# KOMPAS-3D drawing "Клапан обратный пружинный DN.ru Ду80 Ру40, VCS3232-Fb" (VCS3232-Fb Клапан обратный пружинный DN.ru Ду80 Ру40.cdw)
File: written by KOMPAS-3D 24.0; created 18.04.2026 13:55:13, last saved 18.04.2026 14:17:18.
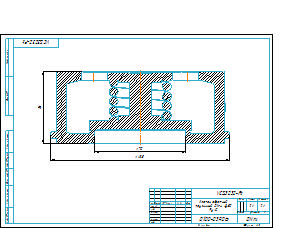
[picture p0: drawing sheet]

Document properties: c3d_UniqueCompID: 071bd168-1a06-425c-849c-e99e84a96128; Наименование: Деталь; Автор: 712; Класс точности: c; Знак неуказанной шероховатости: Шероховатость не задана; Рассекать на разрезах: Да; c3d_UniqueCompID: 071bd168-1a06-425c-849c-e99e84a96128; Наименование: Деталь; Автор: 712; Класс точности: c; Знак неуказанной шероховатости: Шероховатость не задана; Рассекать на разрезах: Да; c3d_UniqueCompID: 071bd168-1a06-425c-849c-e99e84a96128; Наименование: Деталь; Автор: 712; Класс точности: c; Знак неуказанной шероховатости: Шероховатость не задана; Рассекать на разрезах: Да; c3d_UniqueCompID: 071bd168-1a06-425c-849c-e99e84a96128; Наименование: Деталь; Автор: 712; Класс точности: c; Знак неуказанной шероховатости: Шероховатость не задана; Рассекать на разрезах: Да; c3d_UniqueCompID: 071bd168-1a06-425c-849c-e99e84a96128; Наименование: Деталь; Автор: 712; Класс точности: c; Знак неуказанной шероховатости: Шероховатость не задана; Рассекать на разрезах: Да; c3d_UniqueCompID: 071bd168-1a06-425c-849c-e99e84a96128; Наименование: Деталь; Автор: 712; Класс точности: c; Знак неуказанной шероховатости: Шероховатость не задана; Рассекать на разрезах: Да; c3d_UniqueCompID: 071bd168-1a06-425c-849c-e99e84a96128; Наименование: Деталь; Автор: 712; Класс точности: c; Знак неуказанной шероховатости: Шероховатость не задана; Рассекать на разрезах: Да; c3d_UniqueCompID: 071bd168-1a06-425c-849c-e99e84a96128; Наименование: Деталь; Автор: 712; Класс точности: c; Знак неуказанной шероховатости: Шероховатость не задана; Рассекать на разрезах: Да; Автор: 712; Форматы листов документа: A3; Полное имя файла: VCS3232-Fb Клапан обратный пружинный DN.ru Ду80 Ру40.m3d; Масса: 2.1; Наименование: Клапан обратный пружинный DN.ru Ду80 Ру40; Количество листов документа: 1; Примечание: D100-03906

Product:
- Component: Пружина 1086-1017 ГОСТ 18793-80  | qty 1  | additional columns: 3953604318-4147491677-0; Деталь; Пользователь Windows; c; Шероховатость не задана; Да; Сталь 10  ГОСТ 1050-88; source file: Деталь_6.m3d
- Body: Тело 1  | qty 1
    Масса: 2.746242
- Part/product: Клапан обратный пружинный DN.ru Ду80 Ру40  | designation VCS3232-Fb
    Масса: 2.1
    Раздел спецификации: Прочие изделия
    Примечание: D100-03906
    additional columns: 071bd168-1a06-425c-849c-e99e84a96128; Деталь; 712; c; Шероховатость не задана; Да

Views: Вид 1, Местный разрез 1, Спереди
Referenced files in C:\Users\712\Desktop\Новая папка (4)\: VCS3232-Fb Клапан обратный пружинный DN.ru Ду15 Ру40.m3d, VCS3232-Fb Клапан обратный пружинный DN.ru Ду80 Ру40.m3d, VCS3232-Fb Клапан обратный пружинный DN.ru Ду15 Ру40.cdw
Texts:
  VCS3232-Fb
  Клапан обратный
  пружинный DN.ru Ду80
  Ру40
  Клапан обратный пружинный DN.ru Ду80 Ру40
  VCS3232-Fb Клапан обратный пружинный DN.ru Ду80 Ру40
Dimensions and other numbers on the sheet: 0; 3; 2; 4; 138; 70; 56; 2:1; 1; 2,1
